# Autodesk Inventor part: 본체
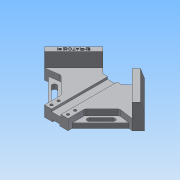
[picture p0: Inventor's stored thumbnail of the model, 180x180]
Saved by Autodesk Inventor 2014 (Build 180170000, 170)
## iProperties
Created: 2020-05
Part Number: 본체
Material: 알루미늄 6061
Document SubType Name: Modeling
Designer: net
Density: 2.71 g/cm^3
Appearance: 알루미늄 - 평지
Mass: 571.604 g
Surface Area: 407.992 cm^2
Volume: 210.924 cm^3
Author: net
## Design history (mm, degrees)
sketch "스케치1"
  geometry: L1 (-84.853, 0)-(84.853, 0); L2 (0, -84.853)-(0, 84.853); L3 (-84.853, 0)-(0, 84.853); L4 (84.853, 0)-(0, 84.853); L5 (-84.853, 0)-(0, -84.853); L6 (0, -84.853)-(84.853, 0); L7 (-35.355, 49.497)-(-16.005, 30.147); L8 (-16.005, 30.147)-(16.005, 30.147); L9 (16.005, 30.147)-(35.355, 49.497); L10 (-20, -64.853)-(20, -64.853); L11 (20, -64.853)-(20, -36.569); L12 (20, -36.569)-(49.497, -7.071); L13 (-20, -64.853)-(-20, -36.569); L14 (-20, -36.569)-(-49.497, -7.071); L15 (68.059, -9.723)-(20, -57.782); L16 (-68.059, -9.723)-(-20, -57.782); L17 (74.246, -10.607)-(24.749, 38.891); L18 (-74.246, -10.607)-(-24.749, 38.891); L19 (-49.497, -7.071)-(-74.246, -10.607); L20 (49.497, -7.071)-(63.64, -21.213); L21 (49.497, -7.071)-(74.246, -10.607); L22 (-49.497, -7.071)-(-63.64, -21.213); 2 further points
  constraints: 44 end point, 14 perpendicular, 14 point on line, 4 parallel, 2 midpoint, 1 coincident, 1 horizontal
  dimensions: "d0" = 120 distance of L1.end L2.end; "d1" = 50 distance from line of L2.end L7; "d2" = 50 distance from line of L9 L2.end; "d3" = 20 distance from line of L2.start L10; "d5" = 95 distance between parallel lines of L10 L8; "d7" = 15 distance of L1.end L17.start; "d8" = 15 distance of L18.start L1.start; "d9" = 20 distance between parallel lines of L5 L14; "d10" = 20 distance between parallel lines of L6 L12; "d11" = 5 distance between parallel lines of L6 L15; "d12" = 5 distance between parallel lines of L5 L16; "d64" = 30 distance of L1.end L20.end; "d65" = 30 distance from line of L1.start L22
extrude "돌출1" new body sketch "스케치1" distance "d13" = 18; taper "d14" = 0 deg
extrude "돌출2" join sketch "스케치1" distance "d15" = 8; taper "d16" = 0 deg
extrude "돌출3" join sketch "스케치1" distance "d17" = 42; taper "d18" = 0 deg
sketch "스케치3"
  geometry: L1 (0, 0)-(-15, 0) reference; L2 (0, 42)-(0, 0) reference; L3 (0, 15)-(-5, 0); 1 further point
  constraints: 2 end point, 2 point on line
  dimensions: "d23" = 5 distance of L1.start L3.end; "d24" = 15 distance of L1.start L3.start
extrude "돌출5" cut sketch "스케치3" stored distance "d25" = 42; taper "d26" = 0 deg
sketch "스케치4"
  geometry: L1 (0, 0)-(40, 0) reference; L2 (0, 18)-(40, 18) reference; L3 (20, 0)-(104.853, 0) reference; L4 (-64.853, 0)-(20, 0) reference; L5 (12, 18)-(12, 13.981); L6 (12, 13.981)-(28, 13.981); L7 (28, 13.981)-(28, 18); L8 (14, 0)-(14, 3); L9 (14, 3)-(26, 3); L10 (26, 3)-(26, 0); 5 further points
  constraints: 12 end point, 6 perpendicular, 4 midpoint, 4 point on line, 2 vertical alignment
  dimensions: "d27" = 16 distance of L5.end L6.end; "d28" = 12 distance of L8.end L9.end; "d29" = 3 distance of L9.end L10.end; "d30" = 4.01851 distance of L6.end L7.end
extrude "돌출6" cut sketch "스케치4" stored distance "d31" = 42; taper "d32" = 0 deg
sketch "스케치5"
  geometry: L1 (-8, -64.853)-(-8, 30.147) reference; L2 (-8, 30.147)-(-16.005, 30.147) reference; L3 (-16.005, 30.147)-(-24.749, 38.891) reference; L4 (-24.749, 38.891)-(-74.246, -10.607) reference; L5 (-74.246, -10.607)-(-49.497, -7.071) reference; L6 (-49.497, -7.071)-(-20, -36.569) reference; L7 (-20, -36.569)-(-20, -64.853) reference; L8 (-20, -64.853)-(-8, -64.853) reference; 2 further points
  dimensions: "d33" = 6 distance from line of L8 point (-14, -58.853); "d34" = 6 distance from line of L7 point (-14, -58.853)
sketch "스케치6"
  geometry: L1 (20, -64.853)-(6, -64.853) reference; L2 (20, -36.569)-(20, -57.782) reference; 3 further points
  constraints: 1 coincident
  dimensions: "d35" = 6 distance from line of L2 point (14, -58.853); "d36" = 6 distance from line of L1 point (14, -58.853)
hole "구멍1" sketch "스케치6" at (14, -58.853) diameter "d37" = 4.5; stored, may be unused: countersink angle "d41" = 90 deg, drill point angle "d43" = 118 deg; dims "d38" = 6, "d39" = 8, "d40" = 10, "d42" = 8
sketch "스케치7"
  geometry: L1 (20, -36.569)-(49.497, -7.071) reference; L2 (49.497, -18.385)-(29.698, -38.184); L3 (52.326, -21.213)-(32.527, -41.012); L4 (26.87, -35.355)-(46.669, -15.556); L5 (74.246, -10.607)-(84.853, 0) reference; L6 (35.355, 49.497)-(84.853, 0) reference; A1 r 4 centre (49.497, -18.385) between (52.326, -21.213) and (46.669, -15.556); A2 r 4 centre (29.698, -38.184) between (26.87, -35.355) and (32.527, -41.012); 4 further points
  constraints: 8 end point, 4 point on circle, 4 tangent, 2 centre point, 2 parallel, 1 midpoint
  dimensions: "d50" = 28 distance of L2.start L2.end; "d52" = 12 distance from line of L5 point (39.598, -28.284); "d53" = 38 distance from line of L6 L2.start; "d61" = 4 radius of A1
extrude "돌출7" cut sketch "스케치7" distance "d54" = 10; taper "d55" = 0 deg
sketch "스케치8"
  geometry: L1 (-74.246, -10.607)-(-24.749, 38.891) reference; L2 (-24.749, 38.891)-(-31.82, 45.962) reference; L3 (-44.194, 30.052)-(-65.407, 8.839); L4 (-84.853, 0)-(-35.355, 49.497) reference; L5 (-49.497, 14.142)-(-60.104, 24.749); 2 further points
  constraints: 4 end point, 4 midpoint, 1 perpendicular, 1 other
  dimensions: "d57" = 7.5 distance between parallel lines of L1 L3; "d58" = 30 distance of L3.start L3.end
feature "엠보싱1" sketch "스케치8" dims "d59" = 0.5, "d60" = 0
sketch "스케치9"
  geometry: L1 (0, 42)-(0, 0) reference; L2 (15, 0)-(0, 0) reference; L3 (5, 0)-(0, 15); 1 further point
  constraints: 2 end point, 2 point on line
  dimensions: "d66" = 15 distance of L1.end L3.end; "d67" = 5 distance of L1.end L3.start
extrude "돌출8" cut sketch "스케치9" stored distance "d68" = 10; taper "d69" = 0 deg
extrude "돌출9" cut sketch "스케치1" stored distance "d70" = 10; taper "d71" = 0 deg
fillet "모깎기1" dims "d72" = 5
fillet "모깎기2" dims "d73" = 5
node "솔리드1"
pattern_linear "직사각형 패턴1" dims "d46" = 12, "d49" = 28
mirror "대칭1"
